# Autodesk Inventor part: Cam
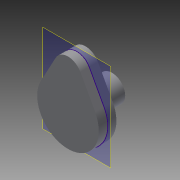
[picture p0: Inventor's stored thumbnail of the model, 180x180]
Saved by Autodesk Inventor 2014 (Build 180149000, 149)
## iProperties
Created: 2006-03
Part Number: Cam
Document SubType Name: Modeling
Designer: debonom
Mass: 14.1538 g
Surface Area: 42.5457 cm^2
Volume: 14.1538 cm^3
Density: 1 g/cm^3
Material: Generic
Appearance: Default
Author: debonom
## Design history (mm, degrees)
sketch "Sketch1"
  geometry: L1 (0, -26.6)-(0, 37.1) reference; L2 (-24.5, 0)-(24.5, 0) reference; L3 (-15.4, 8.312)-(-7.04, 23.8); L4 (7.04, 23.8)-(15.4, 8.312); A1 r 17.5 centre (0, 0) between (-15.4, 8.312) and (15.4, 8.312); A2 r 8 centre (0, 20) between (7.04, 23.8) and (-7.04, 23.8); 1 further point
  constraints: 4 end point, 4 point on circle, 4 tangent, 2 centre point, 1 coincident, 1 point on line
  dimensions: "d0" = 20 distance of point (0, 0) A2.centre; "d1" = 8 radius of A2; "d2" = 17.5 radius of A1
extrude "Extrusion1" new body sketch "Sketch1" distance "d3" = 10; taper "d4" = 0 deg
sketch "Sketch2"
  geometry: C1 r 7.5 at (0, 0); 1 further point
  constraints: 1 centre point, 1 coincident
  dimensions: "d5" = 15 diameter of C1
extrude "Extrusion2" join sketch "Sketch2" distance "d6" = 15; taper "d7" = 0 deg
workplane "Work Plane1"
sketch "Sketch3"
  geometry: L1 (-7.04, -23.8)-(-15.4, -8.312) reference; L2 (15.4, -8.312)-(7.04, -23.8) reference; A1 r 17.5 centre (0, 0) between (15.4, -8.312) and (-15.4, -8.312) reference; A2 r 8 centre (0, -20) between (-7.04, -23.8) and (7.04, -23.8) reference; 1 further point
  constraints: 4 end point, 4 point on circle, 2 centre point, 10 other
body "Solid1"
